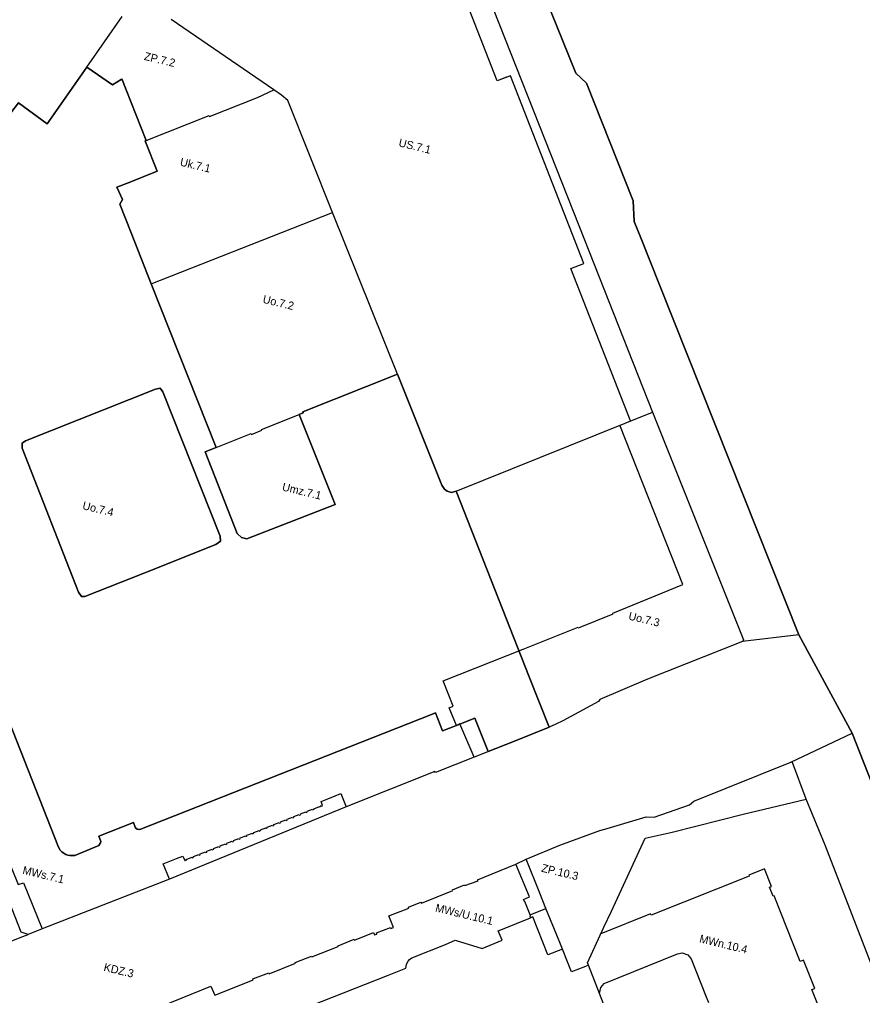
# Model space of a CAD drawing. Extents: x 7429686 to 7432896, y 5547954 to 5550600.
# Drawn here: x 7431781.4 to 7432202.5, y 5549169.6 to 5549657.1 of the extents above; entities that cross this region are included whole.
import ezdxf

# ---------------------------------------------------------------- set-up
doc = ezdxf.new("R2010")
doc.units = 0
for name, color, linetype in [('granica planu', 7, 'Continuous'), ('linie rozgraniczające', 7, 'Continuous'), ('nieprzekraczalna linia zabudowy', 7, 'Continuous'), ('obowiązująca linia zabudowy', 7, 'Continuous'), ('oznaczenia przeznaczeń', 7, 'Continuous')]:
    doc.layers.add(name, color=color, linetype=linetype)

msp = doc.modelspace()

# ---------------------------------------------------------------- linework, layer by layer
at = {"layer": 'granica planu'}
msp.add_line((7432170.68, 5549349.73), (7432197.26, 5549300.66), dxfattribs=at)
for points in [[(7432025.13, 5549714.87), (7432059.26, 5549630.41), (7432064.55, 5549625.33), (7432087.92, 5549566.51), (7432088.5, 5549556.18), (7432091.7, 5549548.15), (7432101.09, 5549524.55), (7432170.68, 5549349.73)], [(7432197.26, 5549300.66), (7432203.11, 5549285.85), (7432253.35, 5549158.49)]]:
    msp.add_lwpolyline(points, dxfattribs=at)
at = {"layer": 'linie rozgraniczające'}
for p, q in [((7431815.03, 5549633.4), (7431795.29, 5549605.07)), ((7431827.84, 5549624.59), (7431815.03, 5549633.4)), ((7431844.23, 5549596.57), (7431844.69, 5549596.76)), ((7431844.41, 5549596.11), (7431844.23, 5549596.57)), ((7431879.65, 5549443.31), (7431847.24, 5549525.12)), ((7431970.17, 5549479.91), (7431922.91, 5549461.22)), ((7431992.36, 5549424.57), (7431970.17, 5549479.91)), ((7431921.05, 5549459.87), (7431939.01, 5549414.82)), ((7431993.65, 5549422.57), (7431992.36, 5549424.57)), ((7431999.58, 5549421.56), (7431997.16, 5549420.89)), ((7432036.03, 5549328.84), (7431999.58, 5549421.56)), ((7431939.01, 5549414.82), (7431894.9, 5549397.77)), ((7431892.21, 5549398.3), (7431890.17, 5549400.41)), ((7431881.72, 5549396.49), (7431879.46, 5549394.92)), ((7431894.9, 5549397.77), (7431892.21, 5549398.3)), ((7432045.92, 5549303.61), (7432036.03, 5549328.84)), ((7432001.66, 5549305.25), (7432008.84, 5549308.09)), ((7432008.84, 5549308.09), (7432015.44, 5549291.5)), ((7432015.44, 5549291.5), (7432015.47, 5549291.43))]:
    msp.add_line(p, q, dxfattribs=at)
for points in [[(7432170.68, 5549349.73), (7432101.09, 5549524.55), (7432091.7, 5549548.15), (7432088.5, 5549556.18), (7432087.92, 5549566.51), (7432064.55, 5549625.33), (7432059.26, 5549630.41), (7432025.13, 5549714.87), (7432023.35, 5549718.94), (7432016.93, 5549731.12), (7432011.47, 5549739.51), (7432005.61, 5549747.16), (7432002.88, 5549750.78), (7431999.04, 5549755.42), (7431989.27, 5549765.25), (7431986.1, 5549768.47), (7431982.62, 5549771.59), (7431983.7, 5549773.53), (7431976.11, 5549778.51), (7431955.59, 5549792.81), (7431858.59, 5549842.92), (7431852.56, 5549864.15)], [(7432003.86, 5549698.45), (7432063.67, 5549547.01)], [(7431815.03, 5549633.4), (7431832.75, 5549658.62)], [(7431908.38, 5549622.06), (7431857.23, 5549657.14)], [(7431715.54, 5549629.72), (7431727.32, 5549637.84), (7431734.7, 5549632.58), (7431761.71, 5549614.21), (7431764.98, 5549611.87), (7431773.29, 5549605.48), (7431780.86, 5549615.54), (7431795.29, 5549605.07), (7431815.03, 5549633.4)], [(7431815.03, 5549633.4), (7431827.84, 5549624.59)], [(7431832.54, 5549627.49), (7431832.11, 5549627.22), (7431827.84, 5549624.59)], [(7431827.84, 5549624.59), (7431832.11, 5549627.22)], [(7431832.11, 5549627.22), (7431832.54, 5549627.49)], [(7431844.69, 5549596.76), (7431834.71, 5549621.99), (7431832.54, 5549627.49)], [(7431832.54, 5549627.49), (7431834.71, 5549621.99)], [(7431834.71, 5549621.99), (7431844.69, 5549596.76)], [(7431900.35, 5549618.11), (7431908.38, 5549622.06)], [(7431912.22, 5549619.43), (7431908.38, 5549622.06)], [(7431915.37, 5549616.66), (7431912.22, 5549619.43)], [(7431795.29, 5549605.07), (7431780.86, 5549615.54), (7431773.29, 5549605.48), (7431764.98, 5549611.87)], [(7431876.3, 5549608.65), (7431900.35, 5549618.11)], [(7431937.8, 5549560.69), (7431915.37, 5549616.66)], [(7431844.69, 5549596.76), (7431876.13, 5549609.12)], [(7431876.13, 5549609.12), (7431876.3, 5549608.65)], [(7431847.24, 5549525.12), (7431837.14, 5549550.6), (7431831.5, 5549564.84), (7431832.81, 5549567.23), (7431830.06, 5549573.32), (7431836.12, 5549575.74), (7431850.24, 5549581.36), (7431844.41, 5549596.11)], [(7431844.41, 5549596.11), (7431850.24, 5549581.36), (7431836.12, 5549575.74), (7431830.06, 5549573.32), (7431832.81, 5549567.23), (7431831.5, 5549564.84), (7431837.14, 5549550.6), (7431847.24, 5549525.12)], [(7431844.69, 5549596.76), (7431844.23, 5549596.57), (7431844.41, 5549596.11)], [(7431847.24, 5549525.12), (7431937.8, 5549560.69)], [(7431970.17, 5549479.91), (7431937.8, 5549560.69)], [(7432063.67, 5549547.01), (7432097.64, 5549461.01)], [(7431847.24, 5549525.12), (7431879.65, 5549443.31)], [(7431921.05, 5549459.87), (7431923.14, 5549460.62), (7431922.91, 5549461.22), (7431970.17, 5549479.91)], [(7431970.17, 5549479.91), (7431992.36, 5549424.57), (7431993.65, 5549422.57), (7431995.04, 5549421.56), (7431997.16, 5549420.89), (7431999.58, 5549421.56)], [(7431881.72, 5549396.49), (7431881.64, 5549399.02), (7431853.07, 5549471.22), (7431851.66, 5549472.92), (7431849.28, 5549472.41), (7431784.41, 5549446.68), (7431782.67, 5549445.45), (7431782.66, 5549442.93), (7431810.87, 5549371.07), (7431812.42, 5549368.97), (7431814.05, 5549368.83)], [(7431814.05, 5549368.83), (7431812.42, 5549368.97), (7431810.87, 5549371.07), (7431782.66, 5549442.93), (7431782.67, 5549445.45), (7431784.41, 5549446.68), (7431849.28, 5549472.41), (7431851.66, 5549472.92), (7431853.07, 5549471.22), (7431881.64, 5549399.02), (7431881.72, 5549396.49)], [(7431879.65, 5549443.31), (7431874.06, 5549441.11), (7431890.17, 5549400.41), (7431892.21, 5549398.3), (7431894.9, 5549397.77), (7431939.01, 5549414.82), (7431921.05, 5549459.87)], [(7431902.26, 5549452.4), (7431921.05, 5549459.87)], [(7431922.91, 5549461.22), (7431923.14, 5549460.62), (7431921.05, 5549459.87)], [(7431999.58, 5549421.56), (7432097.64, 5549461.01)], [(7432097.64, 5549461.01), (7432143.03, 5549347.33)], [(7431879.65, 5549443.31), (7431897.12, 5549450.29)], [(7431897.12, 5549450.29), (7431897.3, 5549449.86)], [(7431897.3, 5549449.86), (7431902.43, 5549451.97)], [(7431902.43, 5549451.97), (7431902.26, 5549452.4)], [(7431890.17, 5549400.41), (7431874.06, 5549441.11), (7431879.65, 5549443.31)], [(7431997.16, 5549420.89), (7431995.04, 5549421.56), (7431993.65, 5549422.57)], [(7431999.58, 5549421.56), (7432036.03, 5549328.84), (7432045.92, 5549303.61)], [(7431814.05, 5549368.83), (7431844.03, 5549380.78), (7431879.46, 5549394.92), (7431881.72, 5549396.49)], [(7431879.46, 5549394.92), (7431844.03, 5549380.78), (7431814.05, 5549368.83)], [(7432142.47, 5549346.46), (7432095.13, 5549327.63)], [(7432170.68, 5549349.73), (7432142.47, 5549346.46)], [(7432143.03, 5549347.33), (7432142.47, 5549346.46)], [(7432197.26, 5549300.66), (7432170.68, 5549349.73)], [(7431759.74, 5549328.57), (7431763.07, 5549320.56), (7431765.54, 5549321.5), (7431769.26, 5549322.91), (7431771.9, 5549315.98), (7431772.38, 5549316.19), (7431800.94, 5549243.7)], [(7432095.13, 5549327.63), (7432071.36, 5549317.43)], [(7432071.36, 5549317.43), (7432070.67, 5549316.48)], [(7432015.44, 5549291.5), (7432008.84, 5549308.09), (7432001.66, 5549305.25), (7431999.6, 5549304.45), (7431992.65, 5549301.73), (7431989.17, 5549310.73), (7431987.21, 5549310.02), (7431841.54, 5549252.53), (7431840.21, 5549252.74), (7431839.57, 5549253.09), (7431839.19, 5549253.59), (7431838.26, 5549255.92), (7431821.08, 5549249.13), (7431821.91, 5549247.07), (7431821.98, 5549246.44), (7431821.84, 5549245.76), (7431821.04, 5549244.46), (7431809.08, 5549239.58), (7431807.79, 5549239.44), (7431806.62, 5549239.48), (7431805.56, 5549239.72), (7431804.57, 5549240.06), (7431803.67, 5549240.53), (7431802.52, 5549241.35), (7431801.7, 5549242.15), (7431800.94, 5549243.7), (7431772.38, 5549316.19)], [(7432070.67, 5549316.48), (7432056.75, 5549308.95)], [(7431800.94, 5549243.7), (7431801.7, 5549242.15), (7431802.52, 5549241.35), (7431803.67, 5549240.53), (7431804.57, 5549240.06), (7431805.56, 5549239.72), (7431806.62, 5549239.48), (7431807.79, 5549239.44), (7431809.08, 5549239.58), (7431821.04, 5549244.46), (7431821.84, 5549245.76), (7431821.98, 5549246.44), (7431821.91, 5549247.07), (7431821.08, 5549249.13), (7431838.26, 5549255.92), (7431839.19, 5549253.59), (7431839.57, 5549253.09), (7431840.21, 5549252.74), (7431841.54, 5549252.53), (7431987.21, 5549310.02)], [(7431987.21, 5549310.02), (7431989.17, 5549310.73), (7431992.65, 5549301.73)], [(7432056.75, 5549308.95), (7432052.86, 5549306.85)], [(7431992.65, 5549301.73), (7431999.6, 5549304.45), (7432001.66, 5549305.25)], [(7432015.47, 5549291.43), (7432027.76, 5549296.37), (7432045.92, 5549303.61)], [(7432045.92, 5549303.61), (7432027.76, 5549296.37), (7432015.47, 5549291.43)], [(7432049.38, 5549305.12), (7432045.92, 5549303.61)], [(7432052.86, 5549306.85), (7432049.38, 5549305.12)], [(7432166.66, 5549286.2), (7432197.26, 5549300.66)], [(7432253.35, 5549158.49), (7432203.11, 5549285.85), (7432197.26, 5549300.66)], [(7432008.52, 5549288.7), (7431989.12, 5549281)], [(7432014.85, 5549291.18), (7432008.52, 5549288.7)], [(7432015.47, 5549291.43), (7432014.85, 5549291.18)], [(7432015.47, 5549291.43), (7432015.44, 5549291.5)], [(7431782.16, 5549201.26), (7431749.63, 5549284.08)], [(7432118.21, 5549266.61), (7432166.66, 5549286.2)], [(7432167.53, 5549285.95), (7432166.66, 5549286.2)], [(7432174.42, 5549267.59), (7432167.53, 5549285.95)], [(7431988.93, 5549281.48), (7431944.6, 5549263.85)], [(7431989.12, 5549281), (7431988.93, 5549281.48)], [(7431944.6, 5549263.85), (7431856.3, 5549227.74)], [(7432098.43, 5549258.61), (7432116.08, 5549264.77)], [(7432116.08, 5549264.77), (7432118.21, 5549266.61)], [(7432142.88, 5549260.1), (7432174.42, 5549267.59)], [(7432183.8, 5549244.75), (7432174.42, 5549267.59)], [(7432074.98, 5549253), (7432094.35, 5549258.82)], [(7432094.35, 5549258.82), (7432098.43, 5549258.61)], [(7432107.39, 5549251.21), (7432142.88, 5549260.1)], [(7432051.26, 5549244.73), (7432071.24, 5549251.97)], [(7432071.24, 5549251.97), (7432074.98, 5549253)], [(7432093.94, 5549248.24), (7432107.39, 5549251.21)], [(7432034.48, 5549237.61), (7432051.26, 5549244.73)], [(7432077.13, 5549211.75), (7432093.94, 5549248.24)], [(7432207.69, 5549183.3), (7432183.8, 5549244.75)], [(7432010.25, 5549227.39), (7432029.28, 5549235.23)], [(7432029.28, 5549235.23), (7432034.48, 5549237.61)], [(7432041.25, 5549220.69), (7432034.48, 5549237.61)], [(7431856.3, 5549227.74), (7431792.73, 5549202.85)], [(7431997.7, 5549222.42), (7432003.7, 5549224.94)], [(7432003.7, 5549224.94), (7432003.89, 5549224.47)], [(7432003.89, 5549224.47), (7432010.44, 5549226.92)], [(7432010.44, 5549226.92), (7432010.25, 5549227.39)], [(7431982.18, 5549215.69), (7431997.88, 5549222.01)], [(7431997.88, 5549222.01), (7431997.7, 5549222.42)], [(7432044.33, 5549213.11), (7432041.25, 5549220.69)], [(7431975.71, 5549213.76), (7431981.88, 5549216.18)], [(7431981.88, 5549216.18), (7431982.18, 5549215.69)], [(7431965.94, 5549209.43), (7431975.94, 5549213.28)], [(7431975.94, 5549213.28), (7431975.71, 5549213.76)], [(7432036.45, 5549209.85), (7432044.23, 5549213.06)], [(7432036.66, 5549209.29), (7432036.45, 5549209.85)], [(7432044.23, 5549213.06), (7432044.33, 5549213.11)], [(7432050.97, 5549196.81), (7432044.33, 5549213.11)], [(7432073.33, 5549203.66), (7432077.13, 5549211.75)], [(7431968.14, 5549203.58), (7431965.94, 5549209.43)], [(7432026.86, 5549204.4), (7432029.69, 5549205.5)], [(7432029.69, 5549205.5), (7432036.67, 5549208.4)], [(7432036.41, 5549209.12), (7432036.66, 5549209.29)], [(7432036.67, 5549208.4), (7432036.41, 5549209.12)], [(7431785.68, 5549200.08), (7431782.16, 5549201.26)], [(7431783.03, 5549199.05), (7431785.68, 5549200.08)], [(7431792.73, 5549202.85), (7431785.68, 5549200.08)], [(7431948.81, 5549197.29), (7431958.27, 5549201)], [(7431958.27, 5549201), (7431958.71, 5549199.86)], [(7431958.71, 5549199.86), (7431959.92, 5549200.27)], [(7431959.77, 5549200.82), (7431966.78, 5549203.55)], [(7431959.92, 5549200.27), (7431959.77, 5549200.82)], [(7431966.78, 5549203.55), (7431966.94, 5549203.07)], [(7431966.94, 5549203.07), (7431968.14, 5549203.58)], [(7432020.56, 5549201.96), (7432026.86, 5549204.4)], [(7432022.43, 5549197.2), (7432020.56, 5549201.96)], [(7432065.15, 5549185.92), (7432073.33, 5549203.66)], [(7431742.92, 5549183.29), (7431783.03, 5549199.05)], [(7431940.5, 5549194.4), (7431948.63, 5549197.69)], [(7431948.63, 5549197.69), (7431948.81, 5549197.29)], [(7431977.41, 5549188.38), (7431994.21, 5549195.04)], [(7431994.21, 5549195.04), (7431999.02, 5549197.19)], [(7431999.02, 5549197.19), (7432012.51, 5549193.05)], [(7432012.51, 5549193.05), (7432022.43, 5549197.2)], [(7432057.14, 5549181.38), (7432050.97, 5549196.81)], [(7431927.42, 5549188.85), (7431940.62, 5549194.06)], [(7431940.62, 5549194.06), (7431940.5, 5549194.4)], [(7432073.43, 5549175.63), (7432110.03, 5549190.38)], [(7432110.03, 5549190.38), (7432112.41, 5549190.81)], [(7432112.41, 5549190.81), (7432115.32, 5549189.88)], [(7431906.15, 5549180.48), (7431919.31, 5549185.71)], [(7431919.17, 5549186.11), (7431927.21, 5549189.2)], [(7431919.31, 5549185.71), (7431919.17, 5549186.11)], [(7431927.21, 5549189.2), (7431927.42, 5549188.85)], [(7431974.47, 5549184.01), (7431974.76, 5549185.3)], [(7431974.76, 5549185.3), (7431975.47, 5549186.72)], [(7431975.47, 5549186.72), (7431976.28, 5549187.61)], [(7431976.28, 5549187.61), (7431977.41, 5549188.38)], [(7432065.62, 5549184.7), (7432065.15, 5549185.92)], [(7432115.32, 5549189.88), (7432116.86, 5549187.97)], [(7432116.86, 5549187.97), (7432124.05, 5549169.74)], [(7431897.9, 5549177.84), (7431905.95, 5549180.95)], [(7431905.95, 5549180.95), (7431906.15, 5549180.48)], [(7431965.2, 5549179.6), (7431974.43, 5549183.24)], [(7431974.43, 5549183.24), (7431974.47, 5549184.01)], [(7432064.17, 5549184.13), (7432057.14, 5549181.38)], [(7432065.62, 5549184.7), (7432064.17, 5549184.13)], [(7432071.12, 5549170.55), (7432065.62, 5549184.7)], [(7431888.58, 5549173.5), (7431898.09, 5549177.43)], [(7431898.09, 5549177.43), (7431897.9, 5549177.84)], [(7431899.21, 5549153.61), (7431965.2, 5549179.6)], [(7432071.79, 5549173.53), (7432073.43, 5549175.63)], [(7431852.81, 5549164.49), (7431877.01, 5549174.22)], [(7431877.01, 5549174.22), (7431879, 5549169.69)], [(7431879, 5549169.69), (7431888.58, 5549173.5)], [(7432071.12, 5549170.55), (7432071.79, 5549173.53)], [(7432093.48, 5549113.01), (7432071.12, 5549170.55)], [(7432124.05, 5549169.74), (7432125.48, 5549166.09)]]:
    msp.add_lwpolyline(points, dxfattribs=at)
at = {"layer": 'nieprzekraczalna linia zabudowy'}
msp.add_line((7432063.33, 5549535.29), (7432026.58, 5549629.01), dxfattribs=at)
for points in [[(7432024.72, 5549628.28), (7432020.07, 5549626.46), (7431993.44, 5549694.37)], [(7432026.58, 5549629.01), (7432020.07, 5549626.46), (7431993.44, 5549694.37)], [(7432086.66, 5549456.6), (7432056.81, 5549532.73), (7432063.33, 5549535.29)]]:
    msp.add_lwpolyline(points, dxfattribs=at)
at = {"layer": 'obowiązująca linia zabudowy'}
for p, q in [((7432112.66, 5549374.87), (7432081.26, 5549454.43)), ((7431783.38, 5549225.92), (7431792.73, 5549202.85))]:
    msp.add_line(p, q, dxfattribs=at)
for points in [[(7432008.52, 5549288.7), (7432001.41, 5549305.24), (7431999.6, 5549304.45), (7431996.09, 5549313.28), (7431998.06, 5549314.07), (7431993, 5549326.85), (7432032.92, 5549342.66), (7432060.53, 5549353.6), (7432060.7, 5549353.17), (7432077.89, 5549360.18), (7432077.72, 5549360.51), (7432112.66, 5549374.87)], [(7431752.23, 5549303.56), (7431749.78, 5549302.56), (7431756.38, 5549285.79), (7431757.78, 5549282.13), (7431764.38, 5549265.55), (7431765.99, 5549261.9), (7431772.7, 5549245.18), (7431774.05, 5549241.57), (7431780.76, 5549224.96), (7431783.38, 5549225.92)], [(7431856.3, 5549227.74), (7431853.18, 5549235.39), (7431856.45, 5549236.68), (7431859.86, 5549237.97), (7431863.06, 5549239.21), (7431864.01, 5549236.98), (7431864.16, 5549237.03), (7431864.06, 5549237.3), (7431864.44, 5549237.46), (7431864.55, 5549237.19), (7431865.01, 5549237.39), (7431864.92, 5549237.66), (7431867.61, 5549238.71), (7431867.72, 5549238.43), (7431868.37, 5549238.69), (7431868.26, 5549238.97), (7431870.96, 5549240.04), (7431871.07, 5549239.76), (7431871.72, 5549240.02), (7431871.61, 5549240.3), (7431874.3, 5549241.37), (7431874.41, 5549241.09), (7431875.06, 5549241.35), (7431874.95, 5549241.63), (7431877.65, 5549242.7), (7431877.76, 5549242.42), (7431878.41, 5549242.68), (7431878.3, 5549242.96), (7431880.99, 5549244.03), (7431881.1, 5549243.75), (7431881.75, 5549244.01), (7431881.64, 5549244.29), (7431884.34, 5549245.36), (7431884.45, 5549245.08), (7431885.1, 5549245.34), (7431884.99, 5549245.62), (7431887.68, 5549246.69), (7431887.79, 5549246.41), (7431888.44, 5549246.67), (7431888.33, 5549246.95), (7431891.03, 5549248.02), (7431891.14, 5549247.74), (7431891.79, 5549248), (7431891.68, 5549248.28), (7431894.37, 5549249.35), (7431894.48, 5549249.07), (7431895.13, 5549249.33), (7431895.02, 5549249.61), (7431897.72, 5549250.68), (7431897.83, 5549250.4), (7431898.48, 5549250.66), (7431898.37, 5549250.94), (7431901.06, 5549252.01), (7431901.17, 5549251.73), (7431901.82, 5549251.99), (7431901.71, 5549252.27), (7431904.41, 5549253.34), (7431904.52, 5549253.06), (7431905.17, 5549253.32), (7431905.06, 5549253.6), (7431907.75, 5549254.67), (7431907.86, 5549254.39), (7431908.51, 5549254.65), (7431908.4, 5549254.93), (7431911.1, 5549256), (7431911.21, 5549255.72), (7431911.86, 5549255.98), (7431911.75, 5549256.26), (7431914.44, 5549257.33), (7431914.55, 5549257.05), (7431915.2, 5549257.31), (7431915.09, 5549257.59), (7431917.79, 5549258.66), (7431917.9, 5549258.38), (7431918.55, 5549258.64), (7431918.44, 5549258.92), (7431921.13, 5549259.99), (7431921.24, 5549259.71), (7431921.89, 5549259.97), (7431921.78, 5549260.25), (7431924.48, 5549261.32), (7431924.59, 5549261.04), (7431925.24, 5549261.3), (7431925.13, 5549261.58), (7431927.82, 5549262.65), (7431927.93, 5549262.37), (7431928.58, 5549262.63), (7431928.47, 5549262.91), (7431931.17, 5549263.98), (7431931.27, 5549263.75), (7431931.77, 5549264), (7431931.7, 5549264.23), (7431932.15, 5549264.44), (7431932.26, 5549264.21), (7431932.8, 5549264.49), (7431932.07, 5549266.57), (7431935.41, 5549267.9), (7431939.01, 5549269.31), (7431941.87, 5549270.44), (7431944.6, 5549263.85)], [(7432052.6, 5549192.74), (7432045.26, 5549189.81), (7432037.75, 5549208.81), (7432036.67, 5549208.4), (7432036.41, 5549209.12), (7432036.66, 5549209.29), (7432036.45, 5549209.85), (7432033.88, 5549216.59), (7432033.58, 5549216.46), (7432033.15, 5549217.54), (7432036.17, 5549218.83), (7432029.28, 5549235.23)], [(7432234.43, 5549030.05), (7432192.34, 5549135.26), (7432191.33, 5549134.86), (7432189.51, 5549139.4), (7432190.28, 5549139.71), (7432177.15, 5549172.52), (7432178.6, 5549173.1), (7432172.97, 5549187.19), (7432171.41, 5549186.57), (7432158.28, 5549219.39), (7432157.78, 5549219.2), (7432156, 5549223.65), (7432157.08, 5549224.08), (7432153.55, 5549232.89), (7432145.69, 5549229.75), (7432145.9, 5549229.24), (7432096.88, 5549209.63), (7432096.59, 5549210.34), (7432071.85, 5549200.44)]]:
    msp.add_lwpolyline(points, dxfattribs=at)

# ---------------------------------------------------------------- texts
at = {"layer": 'oznaczenia przeznaczeń'}
for s, rotation, p in [('ZP.7.2', 346.5122, (7431843.31, 5549637.05)), ('US.7.1', 346.4891, (7431970.5, 5549593.83)), ('Uk.7.1', 346.4891, (7431861.29, 5549584.22)), ('Uo.7.2', 346.4891, (7431902.61, 5549515.67)), ('Umz.7.1', 346.4891, (7431912.3, 5549421.92)), ('Uo.7.4', 346.4891, (7431812.56, 5549412.57)), ('Uo.7.3', 346.4891, (7432085.32, 5549357.44)), ('MWs.7.1', 346.4891, (7431782.65, 5549230.45)), ('ZP.10.3', 346.5122, (7432041.79, 5549231.49)), ('MWs/U.10.1', 346.4891, (7431988.83, 5549211.62)), ('MWn.10.4', 346.4891, (7432120.73, 5549196.18)), ('KDZ.3', 346.4891, (7431823.17, 5549181.98))]:
    msp.add_text(s, height=4, rotation=rotation, dxfattribs=at).set_placement(p)

doc.saveas('drawing.dxf')
